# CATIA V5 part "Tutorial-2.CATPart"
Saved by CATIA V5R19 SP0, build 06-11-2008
Part number: Part1
Bounding box of the stored display mesh (mm): x -50.5 to 35, y -44.738 to 44.738, z 0 to 30.5
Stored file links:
  D:\Shriniwas\v5_r19\c08_cat_v5r19\catia-files\c07-tut02.CATPart
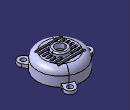
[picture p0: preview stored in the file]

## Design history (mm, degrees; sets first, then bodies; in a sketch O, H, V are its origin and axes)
Body1 (main body)
  Sketch1 on yz-plane, origin (0, 0, 0), H (0, 1, 0), V (0, 0, 1)
    line L1 (0, 0) -> (35, 0)
    line L2 (35, 0) -> (35, 15)
    arc A1 centre (25, 15) radius 10 from (35, 15) to (25, 25) ccw
    line L3 (25, 25) -> (0, 25)
    point P5 (0, 25)
    line L4 (0, 25) -> (0, 0)
    axis line L5 (0, 70.1891) -> (0, -36.6898)
    point P6 (0, 70.1891)
    "Radius" L2 L5 = 35
    distance L1 L3 = 25
    radius A1 = 10
    horizontal: L1 H
    vertical: L2 V, L4 V, L5 V
    tangency: A1 L2, L3 A1
    coincidence: P5 V, P6 V
  Shaft1: profile Sketch1, axis Sketch1.L5, angle 360
  Shell1: ExtOffset 0, IntOffset 2.5, Face face of Shaft1
  Sketch2 on face of Shaft1, origin (0, 0, 0), H (1, 0, 0), V (0, -1, 0)
    projected circle E1 centre (0, 0) radius 35 from edge [face of Shaft1 | face of Shaft1]
    projected arc E2 centre (0, 0) radius 35 from (-34.0735, 8) to (-34.0735, -8) ccw from edge [face of Shaft1 | face of Shaft1]
    point P1 (-34.0735, 8)
    line L1 (-34.0735, 8) -> (-42.5, 8)
    arc A1 centre (-42.5, 0) radius 8 from (-42.5, 8) to (-42.5, -8) ccw
    point P3 (-42.5, 0)
    line L2 (-42.5, -8) -> (-34.0735, -8)
    point P5 (-34.0735, -8)
    circle A2 centre (-42.5, 0) radius 4
    distance P3 V = 42.5
    radius A1 = 8
    radius A2 = 4
    coincidence: P1 E1, P5 E1, P3 H
    horizontal: L1 H, L2 H
    tangency: A1 L1, L2 A1
  Pad1: profile Sketch2, direction (0, 0, 1), length 5
  CircPattern1: of Pad1, instances 3, angular step 120 {= 360.0*1 deg/CircPattern1.AngularNumber}, axis from face of Shaft1
  Sketch3 on face of Shaft1, origin (0, 0, 25), H (1, 0, 0), V (0, 1, 0)
    construction line L1 (-20, -18) -> (20, -18)
    point P2 (20, -18)
    line L2 (-20, -16.25) -> (20, -16.25)
    line L3 (20, -19.75) -> (-20, -19.75)
    arc A1 centre (20, -18) radius 1.75 from (20, -16.25) to (20, -19.75) cw
    arc A2 centre (-20, -18) radius 1.75 from (-20, -19.75) to (-20, -16.25) cw
    length L1 = 40
    distance H L1 = 18
    distance P2 V = 20
    distance L3 L2 = 3.5
    horizontal: L1 H
    tangency: A1 L2, A2 L2, A1 L3, A2 L3
    parallelism: L1 L2
  Pocket1: profile Sketch3, direction (0, 0, -1), length 5
  RectPattern1: of Pocket1, direction 1 instances 7, spacing 6, along yz-plane
  Sketch4 on face of Shell1, origin (0, 0, 22.5), H (1, 0, 0), V (0, -1, 0)
    circle A1 centre (0, 0) radius 12.5
    radius A1 = 12.5
  Pad2: profile Sketch4, direction (0, 0, 1), length 8
  Fillet1: radius 2, on edge [end face of Pad2 | face of Pad2 from Sketch4.A1]
  Sketch5 on face of Pad2, origin (0, 0, 22.5), H (1, 0, 0), V (0, -1, 0)
    circle A1 centre (0, 0) radius 7.5
    radius A1 = 7.5
  Pocket2: profile Sketch5, direction (0, 0, 1), through (limit type 3)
